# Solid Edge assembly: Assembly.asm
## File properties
Author: Administrator
Template: Normal.asm
Last saved by: SOFT
Revision: 29
Application: Solid Edge
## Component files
Stock_support_base.par
thrust_bearing.par
adjusting_screw_nut.par
support_adjusting_screw.par
support_roller_bracket.par
stock_support_roller.par
adjusting_nut_handle.par
adjusting_screw_guide.par
